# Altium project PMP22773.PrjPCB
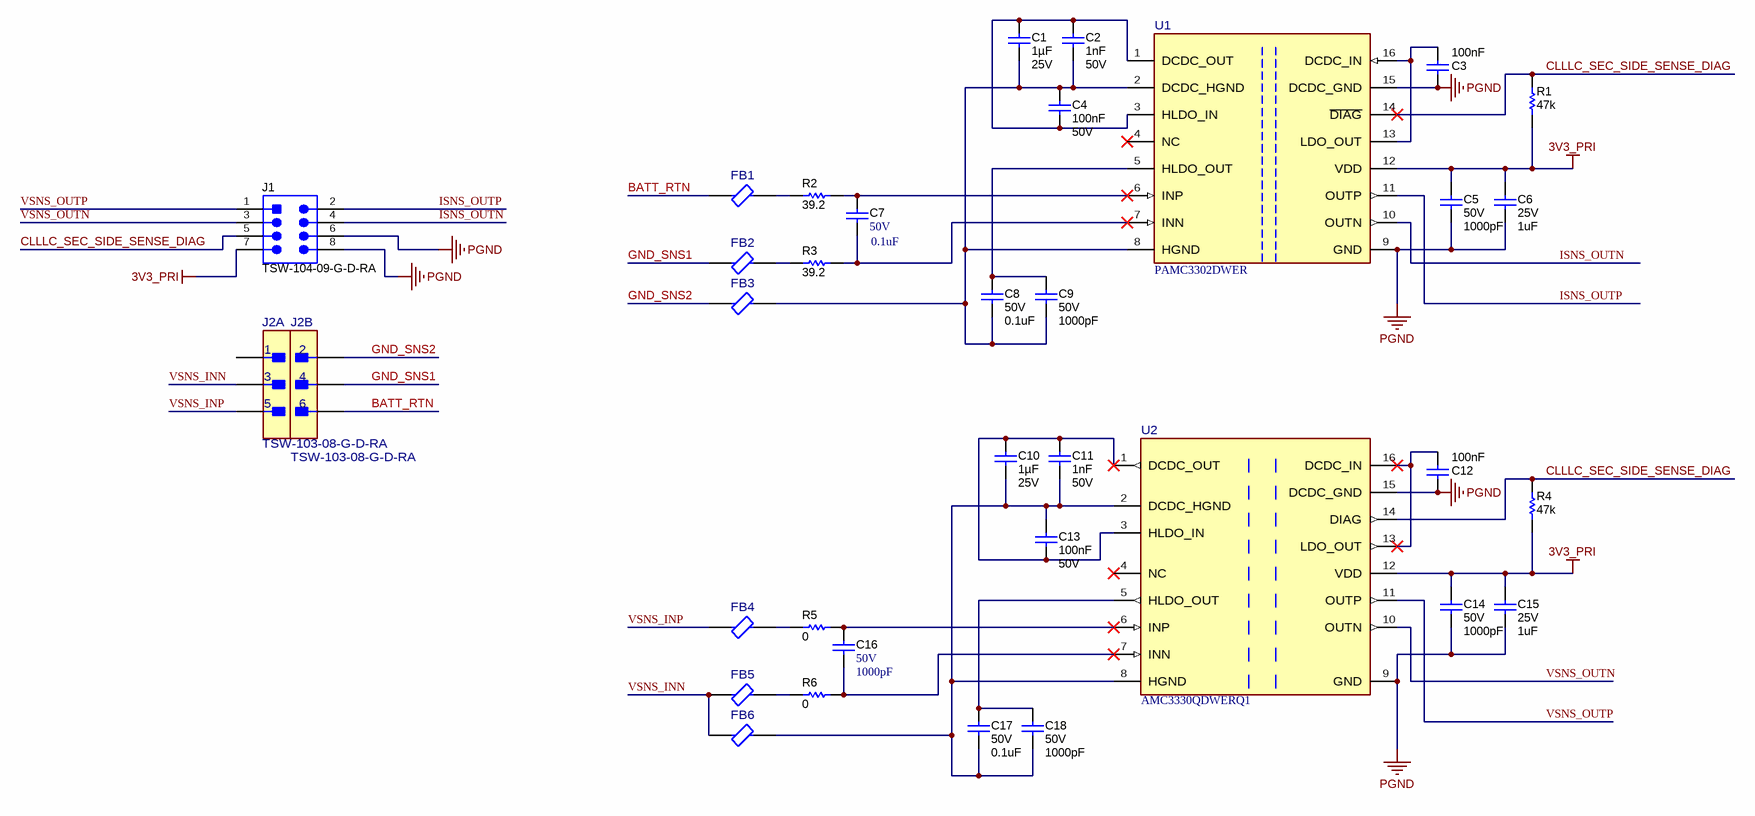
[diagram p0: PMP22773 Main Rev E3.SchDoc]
TID: N/A; TechSupport: http://www.ti.com/support; SCH_Rev: E3; PRJ_Title: Automotive Isolated Sensing Daughter Card; PRJ_Number: PMP22773; PRJ_Engineer: B McDonald; PRJ_Customer: Public Release; PCB_Rev: E3; CopyrightYear: 2021
1 sheet, 34 parts. Net scope: global (net labels, ports and power ports of the same name join across sheets).
Board file: PMP22773 Rev E3 PCB.PcbDoc

## Sheet PMP22773 Main Rev E3.SchDoc
size 431 x 279 mm; Date: Not shown in title block; ApprovedBy: Not shown in title block; CheckedBy: Not shown in title block; Author: Not shown in title block; CompanyName: Not shown in title block; Engineer: Not shown in title block; Organization: Not shown in title block; Address1: Not shown in title block; Address2: Not shown in title block; Address3: Not shown in title block; Address4: Not shown in title block; DocumentNumber: 2; Revision: Use project parameter SCH_Rev; SheetNumber: 2; SheetTotal: 3; PageSetup: Record=PageOptions¦CenterHorizontal=True¦CenterVertical=True¦PrintScale=1.00¦XCorrection=1.00¦YCorrection=1.00¦PrintKind=0¦BorderSize=5000000¦LeftOffset=0¦BottomOffset=0¦Orientation=2¦PaperLength=1000¦PaperWidth=1000¦Scale=100¦PaperSource=15¦PrintQuality=600¦MediaType=1¦DitherType=10¦PaperKind=Letter¦PrintScaleMode=1

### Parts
C1  Cap_F: 1µF  VDC_V: 25V  [0603S]  (hidden comment: CGA3E1X7R1E105K080AC)
C2  Cap_F: 1nF  VDC_V: 50V  [0603]  (hidden comment: C0603C102K5RACTU)
C3  Cap_F: 100nF  [0603]  (hidden comment: C0603C104K5RACAUTO)
C4  Cap_F: 100nF  VDC_V: 50V  [0603]  (hidden comment: C0603C104K5RACAUTO)
C5  VDC_V: 50V  ValueDisplayed: 1000pF  [1206]  (hidden comment: 12065C102KAT2A)
C6  VDC_V: 25V  ValueDisplayed: 1uF  [1206]  (hidden comment: 12063C105KAT2A)
C7  value 0.1uF  VDC_V: 50V  [0402]  (hidden comment: CGA2B3X7R1H104K050BB)
C8  VDC_V: 50V  ValueDisplayed: 0.1uF  [1206_190]  (hidden comment: C3216NP01H104J160AA)
C9  VDC_V: 50V  ValueDisplayed: 1000pF  [1206]  (hidden comment: 12065C102KAT2A)
C10  Cap_F: 1µF  VDC_V: 25V  [0603S]  (hidden comment: CGA3E1X7R1E105K080AC)
C11  Cap_F: 1nF  VDC_V: 50V  [0603]  (hidden comment: C0603C102K5RACTU)
C12  Cap_F: 100nF  [0603]  (hidden comment: C0603C104K5RACAUTO)
C13  Cap_F: 100nF  VDC_V: 50V  [0603]  (hidden comment: C0603C104K5RACAUTO)
C14  VDC_V: 50V  ValueDisplayed: 1000pF  [1206]  (hidden comment: 12065C102KAT2A)
C15  VDC_V: 25V  ValueDisplayed: 1uF  [1206]  (hidden comment: 12063C105KAT2A)
C16  VDC_V: 50V  ValueDisplayed: 1000pF  [0402]  (hidden comment: CGA2B2X7R1H102K050BA)
C17  VDC_V: 50V  ValueDisplayed: 0.1uF  [1206_190]  (hidden comment: C3216NP01H104J160AA)
C18  VDC_V: 50V  ValueDisplayed: 1000pF  [1206]  (hidden comment: 12065C102KAT2A)
FB1  MMZ1005Y182CTD25  [FP-MMZ1005Y182CTD25_0402-MFG]  (value not drawn)
FB2  MMZ1005Y182CTD25  [FP-MMZ1005Y182CTD25_0402-MFG]  (value not drawn)
FB3  MMZ1005Y182CTD25  [FP-MMZ1005Y182CTD25_0402-MFG]  (value not drawn)
FB4  MMZ1005Y182CTD25  [FP-MMZ1005Y182CTD25_0402-MFG]  (value not drawn)
FB5  MMZ1005Y182CTD25  [FP-MMZ1005Y182CTD25_0402-MFG]  (value not drawn)
FB6  MMZ1005Y182CTD25  [FP-MMZ1005Y182CTD25_0402-MFG]  (value not drawn)
J1  TSW-104-09-G-D-RA  [Samtec_TSW-104-09-G-D-RA]
J2  TSW-103-08-G-D-RA  [FP-TSW-103-08-G-D-RA_HDR6-MFG]  (parts A,B of 2)
R1  ValueDisplayed: 47k  [0603]  (hidden comment: CRCW060347K0JNEA)
R2  ValueDisplayed: 39.2  [0402]  (hidden comment: CRCW040239R2FKED)
R3  ValueDisplayed: 39.2  [0402]  (hidden comment: CRCW040239R2FKED)
R4  ValueDisplayed: 47k  [0603]  (hidden comment: CRCW060347K0JNEA)
R5  ValueDisplayed: 0  [0402]  (hidden comment: CRCW04020000Z0ED)
R6  ValueDisplayed: 0  [0402]  (hidden comment: CRCW04020000Z0ED)
U1  PAMC3302DWER  [DWE0016A-MFG]
U2  AMC3330QDWERQ1  [DWE0016A-MFG]

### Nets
3V3_PRI: C5.1 C6.1 C14.1 C15.1 J1.7 R1.1 R4.1 U1.12(VDD) U2.12(VDD)
PGND: C3.2 C5.2 C6.2 C12.2 C14.2 C15.2 J1.6 J1.8 U1.9(GND) U1.15(DCDC_GND) U2.9(GND) U2.15(DCDC_GND)
BATT_RTN: FB1.1 J2.6
CLLLC_SEC_SIDE_SENSE_DIAG: J1.5 R1.2 R4.2 U1.14(~{DIAG}) U2.14(DIAG)
GND_SNS1: FB2.1 J2.4
GND_SNS2: FB3.1 J2.2
ISNS_OUTN: J1.4 U1.10(OUTN)
ISNS_OUTP: J1.2 U1.11(OUTP)
VSNS_INN: FB5.1 FB6.1 J2.3
VSNS_INP: FB4.1 J2.5
VSNS_OUTN: J1.3 U2.10(OUTN)
VSNS_OUTP: J1.1 U2.11(OUTP)
NetC1_1: C1.1 C2.1 C4.2 U1.1(DCDC_OUT) U1.3(HLDO_IN)
NetC1_2: C1.2 C2.2 C4.1 C8.2 C9.2 FB3.2 U1.2(DCDC_HGND) U1.8(HGND)
NetC3_1: C3.1 U1.13(LDO_OUT) U1.16(DCDC_IN)
NetC7_1: C7.1 R3.2 U1.7(INN)
NetC7_2: C7.2 R2.2 U1.6(INP)
NetC8_1: C8.1 C9.1 U1.5(HLDO_OUT)
NetC10_1: C10.1 C11.1 C13.2 U2.1(DCDC_OUT) U2.3(HLDO_IN)
NetC10_2: C10.2 C11.2 C13.1 C17.2 C18.2 FB6.2 U2.2(DCDC_HGND) U2.8(HGND)
NetC12_1: C12.1 U2.13(LDO_OUT) U2.16(DCDC_IN)
NetC16_1: C16.1 R6.2 U2.7(INN)
NetC16_2: C16.2 R5.2 U2.6(INP)
NetC17_1: C17.1 C18.1 U2.5(HLDO_OUT)
NetFB1_2: FB1.2 R2.1
NetFB2_2: FB2.2 R3.1
NetFB4_2: FB4.2 R5.1
NetFB5_2: FB5.2 R6.1

Not connected (* = marked no-connect by the designer): J2 1; U1 4(NC)*; U2 4(NC)*

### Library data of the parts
C1 C10 = CMP-0076705-3: CAP, CERM, 1 µF, 25 V,+/- 10%, X7R, AEC-Q200 Grade 1, 0603; Manufacturer: TDK; SizeAreaWB_mm2: 4.68; SizeArea_mm2: 1.28; AEC Qualified: Y; AEC Category: Q200; Value: 1uF; TaMax_C: 125°C; SizeZ_mm: 1.0; AEC Grade: 1; Polarized: N; TaMin_C: -55°C; SizeY_mm: 0.8; U/M: EA; SizeX_mm: 1.6; Cap_Case: 1.6x0.8x0.8mm
C2 C11 = CMP-0006847-4: CAP, CERM, 1000 pF, 50 V, +/- 10%, X7R, 0603; Manufacturer: Kemet; TaMin_C: -55°C; Polarized: N; SizeAreaWB_mm2: 4.68; Value1: Unknown; U/M: EA; Value: 1000pF; TaMax_C: 125°C; SizeZ_mm: 1; SizeX_mm: 1.6; SizeY_mm: 0.8; SizeArea_mm2: 1.28; AEC Category: Q200
C3 C12 = CMP-0079602-1: CAP, CERM, 0.1 µF, 50 V,+/- 10%, X7R, AEC-Q200 Grade 1, 0603; Manufacturer: Kemet; TaMin_C: -55°C; Polarized: N; SizeAreaWB_mm2: 4.68; U/M: EA; Value: 0.1uF; TaMax_C: 125°C; SizeZ_mm: 1; SizeX_mm: 1.6; SizeY_mm: 0.8; Value2: 50V; SizeArea_mm2: 1.28; AEC Qualified: Y; AEC Category: Q200; ValueDisplayed: 0.1µF
C4 C13 = CMP-0079602-1: CAP, CERM, 0.1 µF, 50 V,+/- 10%, X7R, AEC-Q200 Grade 1, 0603; Manufacturer: Kemet; TaMin_C: -55°C; Polarized: N; SizeAreaWB_mm2: 4.68; U/M: EA; Value: 0.1uF; TaMax_C: 125°C; SizeZ_mm: 1; SizeX_mm: 1.6; SizeY_mm: 0.8; SizeArea_mm2: 1.28; AEC Qualified: Y; AEC Category: Q200; ValueDisplayed: 0.1µF
C5 C9 C14 C18 = CMP-0008530-2: CAP, CERM, 1000 pF, 50 V, +/- 10%, X7R, 1206; Manufacturer: AVX; TaMin_C: -55°C; ESR_ohm: 0.427; Polarized: N; SizeAreaWB_mm2: 10.92; Value1: 0.427 ohm; U/M: EA; Value: 1000pF; TaMax_C: 125°C; SizeZ_mm: 1.35; SizeY_mm: 1.6; SizeArea_mm2: 5.12; Cap_F: 1nF; SizeX_mm: 3.2; AEC Category: Q200
C6 C15 = CMP-0008509-2: CAP, CERM, 1 uF, 25 V, +/- 10%, X7R, 1206; Manufacturer: AVX; TaMin_C: -55°C; ESR_ohm: 13m; Polarized: N; SizeAreaWB_mm2: 10.92; Value1: 0.013 ohm; U/M: EA; Value: 1uF; TaMax_C: 125°C; SizeZ_mm: 1.35; SizeX_mm: 3.2; SizeY_mm: 1.6; SizeArea_mm2: 5.12; Cap_F: 1µF; AEC Category: Q200
C7 = CMP-0006325-2: CAP, CERM, 0.1 uF, 50 V, +/- 10%, X7R, AEC-Q200 Grade 1, 0402; Manufacturer: TDK; TaMin_C: -55°C; ESR_ohm: 39.064m; Polarized: N; SizeAreaWB_mm2: 3; Value1: 0.039064 ohm; U/M: EA; TaMax_C: 125°C; SizeZ_mm: 0.6; SizeX_mm: 1; SizeY_mm: 0.5; AEC Qualified: Y; Cap_F: 100nF; IRMS_A: 814.669mA; AEC Category: Q200
C8 C17 = CMP-0008647-2: CAP, CERM, 0.1 uF, 50 V, +/- 5%, C0G/NP0, 1206_190; Manufacturer: TDK; TaMin_C: -55°C; Polarized: N; SizeAreaWB_mm2: 10.92; Value1: Unknown; U/M: EA; Value: 0.1uF; TaMax_C: 150°C; SizeZ_mm: 1.9; SizeX_mm: 3.2; SizeY_mm: 1.6; Cap_Case: 1206; SizeArea_mm2: 5.12; Cap_F: 100nF; AEC Category: Q200
C16 = CMP-0006314-2: CAP, CERM, 1000 pF, 50 V, +/- 10%, X7R, AEC-Q200 Grade 1, 0402; Manufacturer: TDK; TaMin_C: -55°C; ESR_ohm: 2.2556; Polarized: N; SizeAreaWB_mm2: 3; Value1: 2.25564 ohm; U/M: EA; Value: 1000pF; TaMax_C: 125°C; SizeZ_mm: 0.6; SizeX_mm: 1; SizeY_mm: 0.5; AEC Qualified: Y; Cap_F: 1nF; IRMS_A: 280.466mA; AEC Category: Q200
FB1-FB6 = CMP-0090600-1: 1.8 kOhms @ 100MHz 1 Signal Line Ferrite Bead 0402 (1005 Metric) 150mA 850mOhm; Manufacturer: TDK; DCR_ohm: 0.85; Impedance At Frequency: 1800Ω @ 100MHz; AEC Qualified: Yes; Tolerance_%: 25%; SizeZ_mm: 0.55mm; AEC Grade: Grade 1
J1 = CMP-0075584-2: Header, 100mil, 4x2, Gold, R/A, TH; Manufacturer: Samtec; Pitch_mm: 2.54; Cert_VDE: N; Gender: Male; Cert_CSA: Y; Current_A: 6.3A; Voltage_V: 550V; Row_Count: 2
J2 = CMP-0090622-1: Connector Header Through Hole, Right Angle 6 position 0.100" (2.54mm); Manufacturer: Samtec; ContactFinish: Gold,Nickel; Current_A: 5.7A; Is Female: no; SizeZ_mm: 5.69mm; Voltage_V: 550V; Row_Count: 2; Conn Gender: Male
R1 R4 = CMP-0025814-4: RES, 47 k, 5%, 0.1 W, AEC-Q200 Grade 0, 0603; Manufacturer: Vishay-Dale; Power_W: 100mW; TempCo: 200 ppm/C; Value_Code: 47k0; Value: 47k; EIA_Code: E24; SizeX_mm: 1.6; SizeY_mm: 0.8; SizeZ_mm: 1; Value2: 0.1W; SizeArea_mm2: 1.28; AEC Qualified: Y; VDC_V: 75V; AEC Category: Q200; AEC Grade: 0
R2 R3 = CMP-0026328-2: RES, 39.2, 1%, 0.063 W, AEC-Q200 Grade 0, 0402; Manufacturer: Vishay-Dale; Power_W: 63mW; TempCo: 100 ppm/C; Value_Code: 39R2; Value: 39.2; EIA_Code: E96; SizeX_mm: 1; SizeY_mm: 0.5; SizeZ_mm: 0.6; Value2: 0.063W; AEC Qualified: Y; VDC_V: 50V; AEC Category: Q200; AEC Grade: 0
R5 R6 = CMP-0026822-3: RES, 0, 5%, 0.063 W, AEC-Q200 Grade 0, 0402; Manufacturer: Vishay-Dale; Power_W: 63mW; TempCo: 200 ppm/C; Value_Code: 0000; Value: 0; EIA_Code: E24; SizeX_mm: 1; SizeY_mm: 0.5; SizeZ_mm: 0.6; Value2: 0.063W; AEC Qualified: Y; VDC_V: 50V; AEC Category: Q200
U1 = CMP-0090884-2: ±50-mV input, precision reinforced isolated amplifier with integrated DC/DC converter 16-SOIC -40 to 125; Manufacturer: Texas Instruments; Max Supply Voltage: 5.5V; TaMax_C: +125°C; AEC Qualified: No; SizeZ_mm: 2.65mm; Input Bias Current: -36uA; Number Of Channels: 1; Nominal Supply Current: 27.5-29.5mA; Min Supply Voltage: 3V; Standoff Height: 0.1mm; TaMin_C: -40°C; TJmax_C: +150°C; Response Time: 0.9ms; Input Offset Voltage: 0.1mV; Output Current Per Channel: 14mA; AEC Category: Q200; CompType: IC
U2 = CMP-0090627-1: Precision, ±1-V Input, Reinforced Isolated Amplifier With Integrated DC/DC Converter; Manufacturer: Texas Instruments; Bandwidth: 310kHz; Max Supply Voltage: 5.5V; SizeZ_mm: 2.65mm; TaMax_C: +125°C; Min Supply Voltage: 3V; TaMin_C: -40°C; TJmax_C: +150°C; Nominal Supply Current: 27.5-28.5mA; AEC Grade: Grade 1; AEC Qualified: Yes; Number Of Channels: 1; Standoff Height: 0.1mm; Input Bias Current: 0.01uA

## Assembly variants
001: not fitted C7 C16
